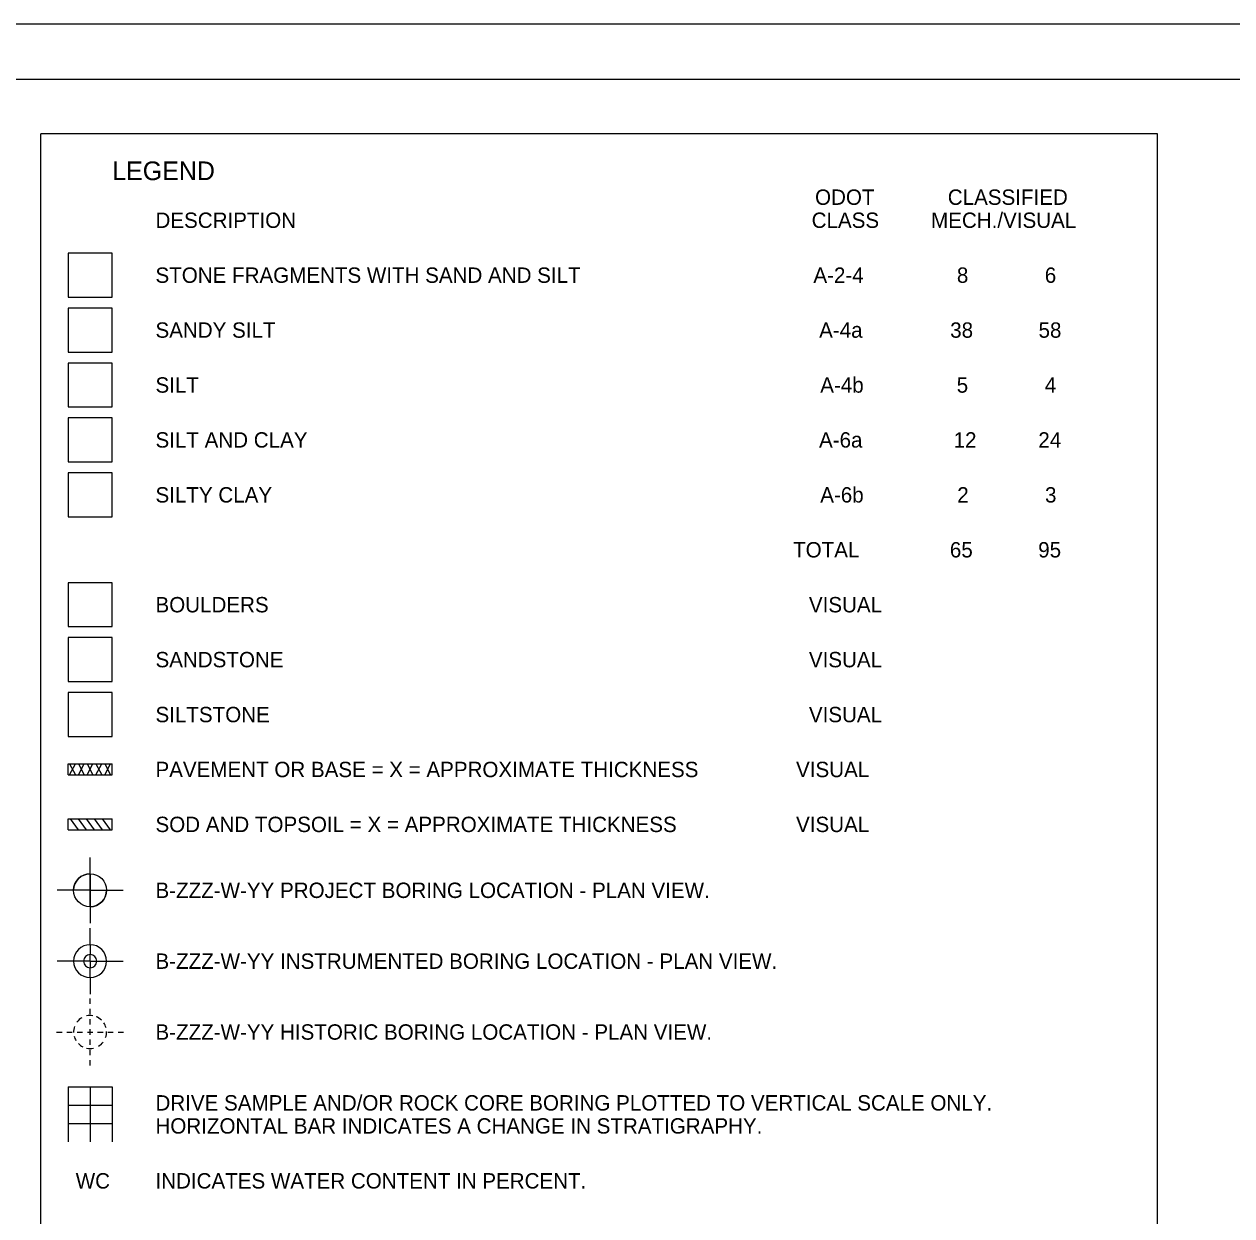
# Model space of a CAD drawing. Extents: x 0 to 34, y 0 to 22.
# Drawn here: x 12.02 to 23.01, y 11.15 to 22 of the extents above; entities that cross this region are included whole.
import ezdxf

# ---------------------------------------------------------------- set-up
doc = ezdxf.new("R2010")
doc.units = 0
for name, color, linetype in [('GT_Historic_Soil_Boring', 7, 'Continuous'), ('GT_Instrumented_Soil_Boring', 7, 'Continuous'), ('GT_Project_Soil_Boring', 7, 'Continuous'), ('GT_Project_Soil_Layers', 7, 'Continuous'), ('SH_Border', 7, 'Continuous'), ('SH_Cut_Line', 7, 'Continuous'), ('SH_Data', 7, 'Continuous'), ('SH_Text', 7, 'Continuous')]:
    doc.layers.add(name, color=color, linetype=linetype)

msp = doc.modelspace()

# ---------------------------------------------------------------- linework, layer by layer
at = {"layer": 'GT_Historic_Soil_Boring'}
for p, q in [((12.617, 13.08), (12.617, 13.13)), ((12.617, 12.987), (12.617, 13.037)), ((12.617, 12.893), (12.617, 12.943)), ((12.312, 12.825), (12.362, 12.825)), ((12.405, 12.825), (12.455, 12.825)), ((12.498, 12.825), (12.548, 12.825)), ((12.592, 12.825), (12.642, 12.825)), ((12.617, 12.8), (12.617, 12.85)), ((12.617, 12.707), (12.617, 12.757)), ((12.685, 12.825), (12.735, 12.825)), ((12.778, 12.825), (12.828, 12.825)), ((12.872, 12.825), (12.922, 12.825)), ((12.617, 12.613), (12.617, 12.663)), ((12.617, 12.52), (12.617, 12.57))]:
    msp.add_line(p, q, dxfattribs=at)
for start, end in [(80.7068, 102.4607), (160.0066, 182.1314), (119.8468, 142.879), (46.3828, 68.4543), (15.179, 33.755), (194.7234, 210.6686), (339.9977, 1.8728), (224.4987, 243.6713), (257.8817, 281.9218), (300.6921, 322.0293)]:
    msp.add_arc((12.617, 12.825), 0.15, start, end, dxfattribs=at)
at = {"layer": 'GT_Instrumented_Soil_Boring'}
for p, q in [((12.617, 13.62), (12.617, 13.77)), ((12.617, 13.62), (12.617, 13.53)), ((12.617, 13.47), (12.617, 13.53)), ((12.467, 13.47), (12.317, 13.47)), ((12.557, 13.47), (12.467, 13.47)), ((12.617, 13.47), (12.557, 13.47)), ((12.617, 13.47), (12.677, 13.47)), ((12.617, 13.47), (12.617, 13.41)), ((12.617, 13.32), (12.617, 13.41)), ((12.677, 13.47), (12.767, 13.47)), ((12.767, 13.47), (12.917, 13.47)), ((12.617, 13.32), (12.617, 13.17))]:
    msp.add_line(p, q, dxfattribs=at)
for radius, start, end in [(0.15, 90, 180), (0.06, 90, 180), (0.15, 0, 90), (0.06, 0, 90), (0.15, 180, 270), (0.06, 180, 270), (0.06, 270, 0), (0.15, 270, 0)]:
    msp.add_arc((12.617, 13.47), radius, start, end, dxfattribs=at)
at = {"layer": 'GT_Project_Soil_Boring'}
for p, q in [((12.617, 14.115), (12.617, 14.415)), ((12.617, 14.265), (12.617, 14.115)), ((12.617, 14.115), (12.317, 14.115)), ((12.617, 14.115), (12.467, 14.115)), ((12.617, 14.115), (12.617, 13.815)), ((12.617, 14.115), (12.917, 14.115)), ((12.617, 13.965), (12.617, 14.115)), ((12.617, 14.115), (12.767, 14.115)), ((12.417, 12.325), (12.817, 12.325)), ((12.417, 12.325), (12.417, 11.825)), ((12.617, 12.325), (12.617, 11.825)), ((12.817, 12.325), (12.817, 11.825)), ((12.417, 12.158), (12.817, 12.158)), ((12.417, 11.992), (12.817, 11.992))]:
    msp.add_line(p, q, dxfattribs=at)
msp.add_circle((12.617, 14.115), 0.15, dxfattribs=at)
for start, end in [(90, 180), (270, 360)]:
    msp.add_arc((12.617, 14.115), 0.15, start, end, dxfattribs=at)
at = {"layer": 'GT_Project_Soil_Layers'}
for p, q in [((12.43, 15.265), (12.483, 15.165)), ((12.43, 15.165), (12.483, 15.265)), ((12.51, 15.265), (12.563, 15.165)), ((12.51, 15.165), (12.563, 15.265)), ((12.59, 15.265), (12.643, 15.165)), ((12.59, 15.165), (12.643, 15.265)), ((12.67, 15.265), (12.723, 15.165)), ((12.67, 15.165), (12.723, 15.265)), ((12.75, 15.265), (12.803, 15.165)), ((12.75, 15.165), (12.803, 15.265)), ((12.435, 14.765), (12.508, 14.665)), ((12.508, 14.765), (12.58, 14.665)), ((12.58, 14.765), (12.653, 14.665)), ((12.653, 14.765), (12.726, 14.665)), ((12.726, 14.765), (12.798, 14.665))]:
    msp.add_line(p, q, dxfattribs=at)
at = {"layer": 'SH_Border'}
msp.add_lwpolyline([(2, 21.5), (33.5, 21.5), (33.5, 0.5), (2, 0.5)], close=True, dxfattribs=at)
at = {"layer": 'SH_Cut_Line'}
msp.add_lwpolyline([(0, 0), (34, 0), (34, 22), (0, 22)], close=True, dxfattribs=at)
at = {"layer": 'SH_Data'}
for p, q in [((12.167, 3.39), (12.167, 21)), ((22.333, 21), (12.167, 21)), ((22.333, 3.39), (22.333, 21)), ((12.417, 15.165), (12.417, 15.265)), ((12.417, 15.265), (12.817, 15.265)), ((12.817, 15.165), (12.817, 15.265)), ((12.417, 15.165), (12.817, 15.165)), ((12.417, 14.765), (12.817, 14.765)), ((12.417, 14.665), (12.417, 14.765)), ((12.817, 14.665), (12.817, 14.765)), ((12.417, 14.665), (12.817, 14.665))]:
    msp.add_line(p, q, dxfattribs=at)
for points in [[(12.417, 19.515), (12.817, 19.515), (12.817, 19.915), (12.417, 19.915)], [(12.417, 19.015), (12.817, 19.015), (12.817, 19.415), (12.417, 19.415)], [(12.417, 18.515), (12.817, 18.515), (12.817, 18.915), (12.417, 18.915)], [(12.417, 18.015), (12.817, 18.015), (12.817, 18.415), (12.417, 18.415)], [(12.417, 17.515), (12.817, 17.515), (12.817, 17.915), (12.417, 17.915)], [(12.417, 16.515), (12.817, 16.515), (12.817, 16.915), (12.417, 16.915)], [(12.417, 16.015), (12.817, 16.015), (12.817, 16.415), (12.417, 16.415)], [(12.417, 15.515), (12.817, 15.515), (12.817, 15.915), (12.417, 15.915)]]:
    msp.add_lwpolyline(points, close=True, dxfattribs=at)

# ---------------------------------------------------------------- texts
at = {"layer": 'SH_Text'}
for s, height, p in [('LEGEND', 0.17, (12.818, 20.58)), ('ODOT', 0.14, (19.215, 20.355)), ('CLASSIFIED', 0.14, (20.423, 20.355)), ('DESCRIPTION', 0.14, (13.212, 20.145)), ('CLASS', 0.14, (19.184, 20.145)), ('MECH./VISUAL', 0.14, (20.271, 20.145)), ('STONE FRAGMENTS WITH SAND AND SILT', 0.14, (13.212, 19.645)), ('A-2-4', 0.14, (19.2, 19.645)), ('8', 0.14, (20.506, 19.645)), ('6', 0.14, (21.306, 19.645)), ('SANDY SILT', 0.14, (13.212, 19.145)), ('A-4a', 0.14, (19.252, 19.145)), ('38', 0.14, (20.445, 19.145)), ('58', 0.14, (21.249, 19.145)), ('SILT', 0.14, (13.212, 18.645)), ('A-4b', 0.14, (19.262, 18.645)), ('5', 0.14, (20.504, 18.645)), ('4', 0.14, (21.306, 18.645)), ('SILT AND CLAY', 0.14, (13.212, 18.145)), ('A-6a', 0.14, (19.251, 18.145)), ('12', 0.14, (20.476, 18.145)), ('24', 0.14, (21.247, 18.145)), ('SILTY CLAY', 0.14, (13.212, 17.645)), ('A-6b', 0.14, (19.262, 17.645)), ('2', 0.14, (20.509, 17.645)), ('3', 0.14, (21.308, 17.645)), ('   TOTAL   ', 0.14, (18.859, 17.145)), ('65', 0.14, (20.442, 17.145)), ('95', 0.14, (21.246, 17.145)), ('BOULDERS', 0.14, (13.212, 16.645)), ('VISUAL', 0.14, (19.159, 16.645)), ('SANDSTONE', 0.14, (13.212, 16.145)), ('VISUAL', 0.14, (19.159, 16.145)), ('SILTSTONE', 0.14, (13.212, 15.645)), ('VISUAL', 0.14, (19.159, 15.645)), ('PAVEMENT OR BASE = X = APPROXIMATE THICKNESS', 0.14, (13.212, 15.145)), ('   VISUAL  ', 0.14, (18.886, 15.145)), ('SOD AND TOPSOIL = X = APPROXIMATE THICKNESS', 0.14, (13.212, 14.645)), ('   VISUAL  ', 0.14, (18.886, 14.645)), ('B-ZZZ-W-YY PROJECT BORING LOCATION - PLAN VIEW.', 0.14, (13.212, 14.045)), ('B-ZZZ-W-YY INSTRUMENTED BORING LOCATION - PLAN VIEW.', 0.14, (13.212, 13.4)), ('B-ZZZ-W-YY HISTORIC BORING LOCATION - PLAN VIEW.', 0.14, (13.212, 12.755)), ('DRIVE SAMPLE AND/OR ROCK CORE BORING PLOTTED TO VERTICAL SCALE ONLY.', 0.14, (13.212, 12.11)), ('HORIZONTAL BAR INDICATES A CHANGE IN STRATIGRAPHY.', 0.14, (13.212, 11.9)), ('WC', 0.14, (12.486, 11.4)), ('INDICATES WATER CONTENT IN PERCENT.', 0.14, (13.212, 11.4))]:
    msp.add_text(s, height=height, dxfattribs=at).set_placement(p)

doc.saveas('drawing.dxf')
